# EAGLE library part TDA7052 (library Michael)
TDA7052 1 Watt Mono Amplifier
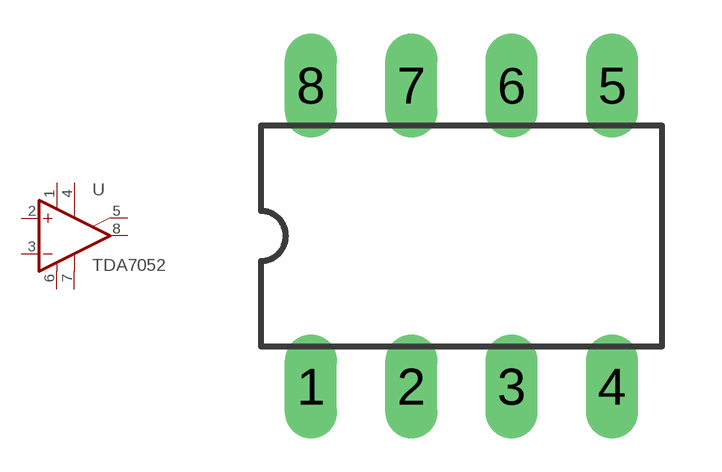
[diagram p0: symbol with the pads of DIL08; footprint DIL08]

Designator prefix -

## TDA7052  [DIL08]
1  V+  pwr
2  +IN  in
3  -IN  in
4  NC1  nc
5  LS1  out
6  V-  pwr
7  NC2  nc
8  LS2  out

## Footprint DIL08 (pad centres in mm)
Dual In Line
drill 0.813 long: 1 -3.81,-3.81; 2 -1.27,-3.81; 3 1.27,-3.81; 4 3.81,-3.81; 5 3.81,3.81; 6 1.27,3.81; 7 -1.27,3.81; 8 -3.81,3.81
